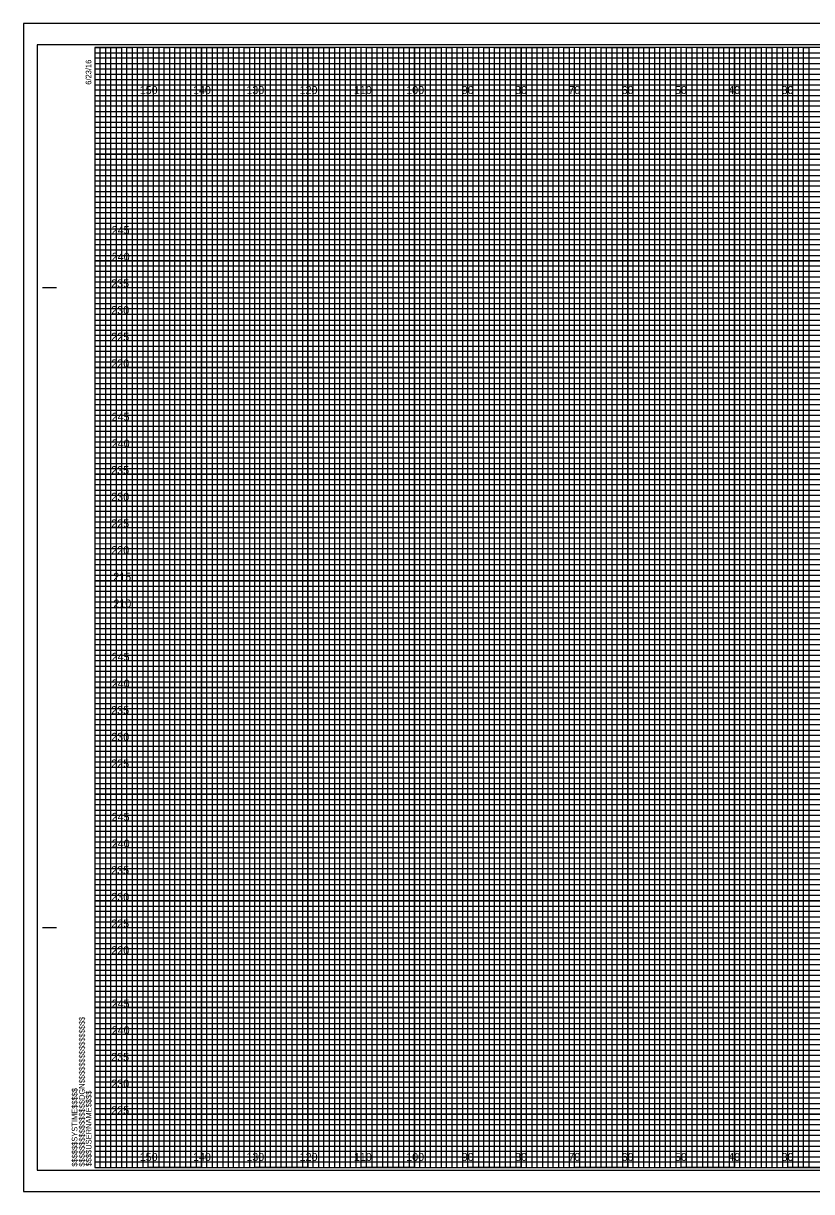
# Model space of a CAD drawing. Extents: x -13 to 323, y -5 to 654.
# Drawn here: x -13.4 to 134.5, y -4.5 to 214.5 of the extents above; entities that cross this region are included whole.
import ezdxf

# ---------------------------------------------------------------- set-up
doc = ezdxf.new("R2010")
doc.units = 0
for name, color, linetype in [('Exist Cross Section Cell', 7, 'Continuous'), ('Exist XS Center Line Elevation Label', 7, 'Continuous'), ('Exist XS Ground Line', 7, 'Continuous'), ('Prop CMT Conc Surface', 7, 'Continuous'), ('Prop CMT Concrete Structures', 7, 'Continuous'), ('Prop CMT DNC', 7, 'Continuous'), ('Prop CMT Pvmt Course 1 Wedge', 7, 'Continuous'), ('Prop CMT Pvmt Course 2', 7, 'Continuous'), ('Prop CMT Pvmt Course 2 Wedge', 7, 'Continuous'), ('Prop CMT Pvmt Course 3', 7, 'Continuous'), ('Prop CMT Subgrade Earthwork', 7, 'Continuous')]:
    doc.layers.add(name, color=color, linetype=linetype)

msp = doc.modelspace()

# ---------------------------------------------------------------- linework, layer by layer
at = {"layer": 'Exist XS Center Line Elevation Label'}
for points in [[(0, 210), (5, 210), (5, 0), (15, 0), (15, 210), (25, 210), (25, 0), (35, 0), (35, 210), (45, 210), (45, 0), (55, 0), (55, 210), (65, 210), (65, 0), (75, 0), (75, 210), (85, 210), (85, 0), (95, 0), (95, 210), (105, 210), (105, 0), (115, 0), (115, 210), (125, 210), (125, 0), (135, 0)], [(0, 205), (275, 205)], [(0, 185), (320, 185), (320, 195), (0, 195)], [(0, 165), (320, 165), (320, 175), (0, 175)], [(0, 145), (320, 145), (320, 155), (0, 155)], [(0, 125), (320, 125), (320, 135), (0, 135)], [(0, 105), (320, 105), (320, 115), (0, 115)], [(0, 85), (320, 85), (320, 95), (0, 95)], [(0, 65), (320, 65), (320, 75), (0, 75)], [(0, 45), (320, 45), (320, 55), (0, 55)], [(0, 25), (320, 25), (320, 35), (0, 35)], [(0, 5), (320, 5), (320, 15), (0, 15)]]:
    msp.add_lwpolyline(points, dxfattribs=at)
at = {"layer": 'Exist XS Ground Line'}
for p, q in [((10, 210), (0, 210)), ((10, 0), (10, 210)), ((30, 210), (20, 210)), ((20, 210), (20, 0)), ((30, 0), (30, 210)), ((50, 210), (40, 210)), ((40, 210), (40, 0)), ((50, 0), (50, 210)), ((70, 210), (60, 210)), ((60, 210), (60, 0)), ((70, 0), (70, 210)), ((90, 210), (80, 210)), ((80, 210), (80, 0)), ((90, 0), (90, 210)), ((110, 210), (100, 210)), ((100, 210), (100, 0)), ((110, 0), (110, 210)), ((130, 210), (120, 210)), ((120, 210), (120, 0)), ((130, 0), (130, 210)), ((20, 0), (10, 0)), ((40, 0), (30, 0)), ((60, 0), (50, 0)), ((80, 0), (70, 0)), ((100, 0), (90, 0)), ((120, 0), (110, 0)), ((140, 0), (130, 0))]:
    msp.add_line(p, q, dxfattribs=at)
for points in [[(0, 200), (320, 200), (320, 190), (0, 190)], [(0, 180), (320, 180), (320, 170), (0, 170)], [(0, 160), (320, 160), (320, 150), (0, 150)], [(0, 140), (320, 140), (320, 130), (0, 130)], [(0, 120), (320, 120), (320, 110), (0, 110)], [(0, 100), (320, 100), (320, 90), (0, 90)], [(0, 80), (320, 80), (320, 70), (0, 70)], [(0, 60), (320, 60), (320, 50), (0, 50)], [(0, 40), (320, 40), (320, 30), (0, 30)], [(0, 20), (320, 20), (320, 10), (0, 10)]]:
    msp.add_lwpolyline(points, dxfattribs=at)
at = {"layer": 'Prop CMT Conc Surface'}
msp.add_lwpolyline([(-13.4, -4.5), (323.3, -4.5), (323.3, 214.5), (-13.4, 214.5)], close=True, dxfattribs=at)
at = {"layer": 'Prop CMT Concrete Structures'}
for p, q in [((-9.8, 165), (-7.3, 165)), ((-9.7, 165), (-7.2, 165)), ((-9.8, 45), (-7.3, 45)), ((-9.7, 45), (-7.2, 45)), ((0, 0), (0, 0)), ((0, 0), (0, 0)), ((0, 0), (0, 0)), ((0, 0), (0, 0)), ((0, 0), (0, 0)), ((0, 0), (0, 0)), ((0, 0), (0, 0))]:
    msp.add_line(p, q, dxfattribs=at)
msp.add_lwpolyline([(320, 210), (0, 210), (0, 0), (320, 0)], close=True, dxfattribs=at)
at = {"layer": 'Prop CMT DNC'}
for points in [[(0, 0), (1, 0), (1, 210), (2, 210), (2, 0)], [(2, 0), (3, 0), (3, 210), (4, 210), (4, 0)], [(5, 0), (6, 0), (6, 210), (7, 210), (7, 0)], [(7, 0), (8, 0), (8, 210), (9, 210), (9, 0)], [(10, 0), (11, 0), (11, 210), (12, 210), (12, 0)], [(12, 0), (13, 0), (13, 210), (14, 210), (14, 0)], [(15, 0), (16, 0), (16, 210), (17, 210), (17, 0)], [(17, 0), (18, 0), (18, 210), (19, 210), (19, 0)], [(20, 0), (21, 0), (21, 210), (22, 210), (22, 0)], [(22, 0), (23, 0), (23, 210), (24, 210), (24, 0)], [(25, 0), (26, 0), (26, 210), (27, 210), (27, 0)], [(27, 0), (28, 0), (28, 210), (29, 210), (29, 0)], [(30, 0), (31, 0), (31, 210), (32, 210), (32, 0)], [(32, 0), (33, 0), (33, 210), (34, 210), (34, 0)], [(35, 0), (36, 0), (36, 210), (37, 210), (37, 0)], [(37, 0), (38, 0), (38, 210), (39, 210), (39, 0)], [(40, 0), (41, 0), (41, 210), (42, 210), (42, 0)], [(42, 0), (43, 0), (43, 210), (44, 210), (44, 0)], [(45, 0), (46, 0), (46, 210), (47, 210), (47, 0)], [(47, 0), (48, 0), (48, 210), (49, 210), (49, 0)], [(50, 0), (51, 0), (51, 210), (52, 210), (52, 0)], [(52, 0), (53, 0), (53, 210), (54, 210), (54, 0)], [(55, 0), (56, 0), (56, 210), (57, 210), (57, 0)], [(57, 0), (58, 0), (58, 210), (59, 210), (59, 0)], [(60, 0), (61, 0), (61, 210), (62, 210), (62, 0)], [(62, 0), (63, 0), (63, 210), (64, 210), (64, 0)], [(65, 0), (66, 0), (66, 210), (67, 210), (67, 0)], [(67, 0), (68, 0), (68, 210), (69, 210), (69, 0)], [(70, 0), (71, 0), (71, 210), (72, 210), (72, 0)], [(72, 0), (73, 0), (73, 210), (74, 210), (74, 0)], [(75, 0), (76, 0), (76, 210), (77, 210), (77, 0)], [(77, 0), (78, 0), (78, 210), (79, 210), (79, 0)], [(80, 0), (81, 0), (81, 210), (82, 210), (82, 0)], [(82, 0), (83, 0), (83, 210), (84, 210), (84, 0)], [(85, 0), (86, 0), (86, 210), (87, 210), (87, 0)], [(87, 0), (88, 0), (88, 210), (89, 210), (89, 0)], [(90, 0), (91, 0), (91, 210), (92, 210), (92, 0)], [(92, 0), (93, 0), (93, 210), (94, 210), (94, 0)], [(95, 0), (96, 0), (96, 210), (97, 210), (97, 0)], [(97, 0), (98, 0), (98, 210), (99, 210), (99, 0)], [(100, 0), (101, 0), (101, 210), (102, 210), (102, 0)], [(102, 0), (103, 0), (103, 210), (104, 210), (104, 0)], [(105, 0), (106, 0), (106, 210), (107, 210), (107, 0)], [(107, 0), (108, 0), (108, 210), (109, 210), (109, 0)], [(110, 0), (111, 0), (111, 210), (112, 210), (112, 0)], [(112, 0), (113, 0), (113, 210), (114, 210), (114, 0)], [(115, 0), (116, 0), (116, 210), (117, 210), (117, 0)], [(117, 0), (118, 0), (118, 210), (119, 210), (119, 0)], [(120, 0), (121, 0), (121, 210), (122, 210), (122, 0)], [(122, 0), (123, 0), (123, 210), (124, 210), (124, 0)], [(125, 0), (126, 0), (126, 210), (127, 210), (127, 0)], [(127, 0), (128, 0), (128, 210), (129, 210), (129, 0)], [(130, 0), (131, 0), (131, 210), (132, 210), (132, 0)], [(132, 0), (133, 0), (133, 210), (134, 210), (134, 0)]]:
    msp.add_lwpolyline(points, dxfattribs=at)
at = {"layer": 'Prop CMT Pvmt Course 1 Wedge'}
for p, q in [((323.3, 214.5), (-13.4, 214.5)), ((-13.4, 214.5), (-13.4, -4.5)), ((-13.4, -4.5), (323.3, -4.5))]:
    msp.add_line(p, q, dxfattribs=at)
at = {"layer": 'Prop CMT Pvmt Course 2'}
msp.add_lwpolyline([(-10.8, -0.5), (322.4, -0.5), (322.4, 210.5), (-10.8, 210.5)], close=True, dxfattribs=at)
at = {"layer": 'Prop CMT Pvmt Course 3'}
for p, q in [((10, 0), (10, 210)), ((20, 0), (20, 210)), ((30, 0), (30, 210)), ((40, 0), (40, 210)), ((50, 0), (50, 210)), ((60, 0), (60, 210)), ((70, 0), (70, 210)), ((80, 0), (80, 210)), ((90, 0), (90, 210)), ((100, 0), (100, 210)), ((110, 0), (110, 210)), ((120, 0), (120, 210)), ((130, 0), (130, 210)), ((0, 200), (320, 200)), ((0, 190), (320, 190)), ((0, 180), (320, 180)), ((0, 170), (320, 170)), ((0, 160), (320, 160)), ((0, 150), (320, 150)), ((0, 140), (320, 140)), ((0, 130), (320, 130)), ((0, 120), (320, 120)), ((0, 110), (320, 110)), ((0, 100), (320, 100)), ((0, 90), (320, 90)), ((0, 80), (320, 80)), ((0, 70), (320, 70)), ((0, 60), (320, 60)), ((0, 50), (320, 50)), ((0, 40), (320, 40)), ((0, 30), (320, 30)), ((0, 20), (320, 20)), ((0, 10), (320, 10))]:
    msp.add_line(p, q, dxfattribs=at)
at = {"layer": 'Prop CMT Subgrade Earthwork'}
for p, q in [((0, 209), (260, 209)), ((260, 207.98), (0, 207.98)), ((0, 207.98), (0, 207)), ((0, 207), (260, 207)), ((260, 205.89), (0, 205.89)), ((0, 205.89), (0, 204)), ((0, 204), (320, 204))]:
    msp.add_line(p, q, dxfattribs=at)
for points in [[(0, 203), (270, 203), (320, 203), (320, 202), (0, 202)], [(0, 201), (320, 201), (320, 199), (0, 199)], [(0, 198), (320, 198), (320, 197), (0, 196.98)], [(0, 196), (320, 196), (320, 194), (0, 194)], [(0, 193), (320, 193), (320, 192), (0, 192)], [(0, 191), (320, 191), (320, 189), (0, 189)], [(0, 188), (320, 188), (320, 187), (0, 187)], [(0, 186), (320, 186), (320, 184), (0, 184)], [(0, 183), (320, 183), (320, 182), (0, 182)], [(0, 181), (320, 181), (320, 179), (0, 179)], [(0, 178), (320, 178), (320, 177), (0, 177)], [(0, 176), (320, 176), (320, 173.95), (320, 173), (320, 172), (0, 172)], [(0, 174), (320, 174), (320, 173), (0, 173)], [(0, 171), (320, 171), (320, 169), (0, 169.03)], [(0, 169.03), (320, 169), (320, 168), (0, 168)], [(0, 167), (320, 167), (320, 166), (0, 166)], [(0, 164), (320, 164), (320, 163), (0, 163)], [(0, 162), (320, 162), (320, 161), (0, 161)], [(-0.07, 158.89), (320, 158.89), (320, 157.88), (-0.07, 157.88)], [(0, 157), (320, 157), (320, 156), (0, 156)], [(0, 154), (320, 154), (320, 153), (0, 153)], [(0, 152), (320, 152), (320, 151), (0, 151)], [(0, 149), (320, 149), (320, 148), (0, 148)], [(0, 147), (320, 147), (320, 146), (0, 146)], [(0, 144), (320, 144), (320, 143), (0, 143)], [(0, 142), (320, 142), (320, 141), (0, 141)], [(0, 139), (320, 139), (319.99, 137.98), (0, 138)], [(0, 137), (320, 137), (320, 136), (0, 136)], [(0, 134), (320, 134), (320, 133), (0, 133)], [(0, 132), (320, 132), (320, 131), (0, 131)], [(0, 129), (320, 129), (320, 128), (0, 128)], [(0, 127), (320, 127), (320, 126), (0, 126)], [(0, 124), (320, 124), (320, 123), (0, 123)], [(0, 122), (320, 122), (320, 121), (0, 121)], [(0, 119), (320, 119), (320, 118), (0, 118)], [(0, 116.99), (320.07, 116.91), (320, 116), (0, 116)], [(0, 114), (320, 114), (320, 113), (0, 113)], [(0, 112), (320, 112), (320, 111), (0, 111)], [(0, 109), (320, 109), (320, 108), (0, 108)], [(0, 107), (320, 107), (320, 106), (0, 106)], [(0, 104), (320, 104), (320, 103), (0, 103)], [(0, 102), (320, 102), (320, 101), (0, 101)], [(0, 99), (320, 99), (320, 98), (0, 98)], [(0, 97), (320, 97), (320, 96), (0, 96)], [(0, 94), (320, 94), (320, 93), (0, 93)], [(0, 92), (320, 92), (320, 91), (0, 91)], [(0, 89), (320, 89), (320, 88), (0, 88)], [(0, 87), (320, 87), (320, 86), (0, 86)], [(0, 84), (320, 84), (320, 83), (0, 83)], [(0, 82), (320, 82), (320, 81), (0, 81)], [(0, 79), (320, 79), (319.99, 77.98), (0, 78)], [(0, 77), (320, 77), (320, 76), (0, 76)], [(0, 74), (320, 74), (320, 73), (0, 73)], [(0, 72), (320, 72), (320, 71), (0, 71)], [(0, 69), (320, 69), (320, 68), (0, 68)], [(0, 67), (320, 67), (320, 66), (0, 66)], [(0, 64), (320, 64), (320, 63), (0, 63)], [(0, 62), (320, 62), (320, 61), (0, 61)], [(0, 59), (320, 59), (320, 58), (0, 58)], [(0, 56.99), (320.07, 56.91), (320, 56), (0, 56)], [(0, 54), (320, 54), (320, 53), (0, 53)], [(0, 52), (320, 52), (320, 51), (0, 51)], [(0, 49), (320, 49), (320, 48), (0, 48)], [(0, 47), (320, 47), (320, 46), (0, 46)], [(0, 44), (320, 44), (320, 43), (0, 43)], [(0, 42), (320, 42), (320, 41), (0, 41)], [(0, 39), (320, 39), (320, 38), (0, 38)], [(0, 37), (320, 37), (320, 36), (0, 36)], [(0, 34), (320, 34), (320, 33), (0, 33)], [(0, 32), (320, 32), (320, 31), (0, 31)], [(0, 29), (320, 29), (320, 28), (0, 28)], [(0, 27), (320, 27), (320, 26), (0, 26)], [(0, 24), (320, 24), (320, 23), (0, 23)], [(0, 22), (320, 22), (320, 21), (0, 21)], [(0, 19), (320, 19), (320, 18), (0, 18)], [(0, 17), (320, 17), (320, 16), (0, 16)], [(0, 14), (320, 14), (320, 13), (0, 13)], [(0, 12), (320, 12), (320, 11), (0, 11)], [(0, 9), (320, 9), (320, 8), (0, 8)], [(0, 7), (320, 7), (320, 6), (0, 6)], [(0, 4), (320, 4), (320, 3), (0, 3)], [(0, 2), (320, 2), (320, 1), (0, 1)]]:
    msp.add_lwpolyline(points, dxfattribs=at)

# ---------------------------------------------------------------- texts
at = {"layer": 'Exist Cross Section Cell'}
for s, p in [('150', (8.44, 201.25)), ('140', (18.44, 201.25)), ('130', (28.44, 201.25)), ('120', (38.44, 201.25)), ('110', (48.62, 201.25)), ('100', (58.44, 201.25)), ('90', (68.86, 201.25)), ('80', (78.86, 201.25)), ('70', (88.86, 201.25)), ('60', (98.86, 201.25)), ('50', (108.86, 201.25)), ('40', (118.86, 201.25)), ('30', (128.86, 201.25)), ('150', (8.44, 1.25)), ('140', (18.44, 1.25)), ('130', (28.44, 1.25)), ('120', (38.44, 1.25)), ('110', (48.62, 1.25)), ('100', (58.44, 1.25)), ('90', (68.86, 1.25)), ('80', (78.86, 1.25)), ('70', (88.86, 1.25)), ('60', (98.86, 1.25)), ('50', (108.86, 1.25)), ('40', (118.86, 1.25)), ('30', (128.86, 1.25))]:
    msp.add_text(s, height=1.5, dxfattribs=at).set_placement(p)
at = {"layer": 'Prop CMT Concrete Structures'}
for s, p in [('6/23/16', (-0.65, 203)), ('$$$$$$$$$$$$$$$$DGN$$$$$$$$$$$$$$$$', (-1.88, 0.18)), ('$$$$$$SYSTIME$$$$$', (-3.26, 0.18)), ('$$$$USERNAME$$$$', (-0.62, 0.23))]:
    msp.add_text(s, height=1.05, rotation=90, dxfattribs=at).set_placement(p)
at = {"layer": 'Prop CMT Pvmt Course 2 Wedge'}
for s, p in [('245', (3.18, 175)), ('240', (3.19, 170)), ('235', (3.09, 165)), ('230', (3.11, 160)), ('225', (3.1, 155)), ('220', (3.12, 150)), ('245', (3.18, 140)), ('240', (3.19, 135)), ('235', (3.09, 130)), ('230', (3.11, 125)), ('225', (3.1, 120)), ('220', (3.12, 115)), ('215', (3.48, 110)), ('210', (3.5, 105)), ('245', (3.18, 95)), ('240', (3.19, 90)), ('235', (3.09, 85)), ('230', (3.11, 80)), ('225', (3.1, 75)), ('245', (3.18, 65)), ('240', (3.19, 60)), ('235', (3.09, 55)), ('230', (3.11, 50)), ('225', (3.1, 45)), ('220', (3.12, 40)), ('245', (3.18, 30)), ('240', (3.19, 25)), ('235', (3.09, 20)), ('230', (3.11, 15)), ('225', (3.1, 10))]:
    msp.add_text(s, height=1.5, dxfattribs=at).set_placement(p)

doc.saveas('drawing.dxf')
